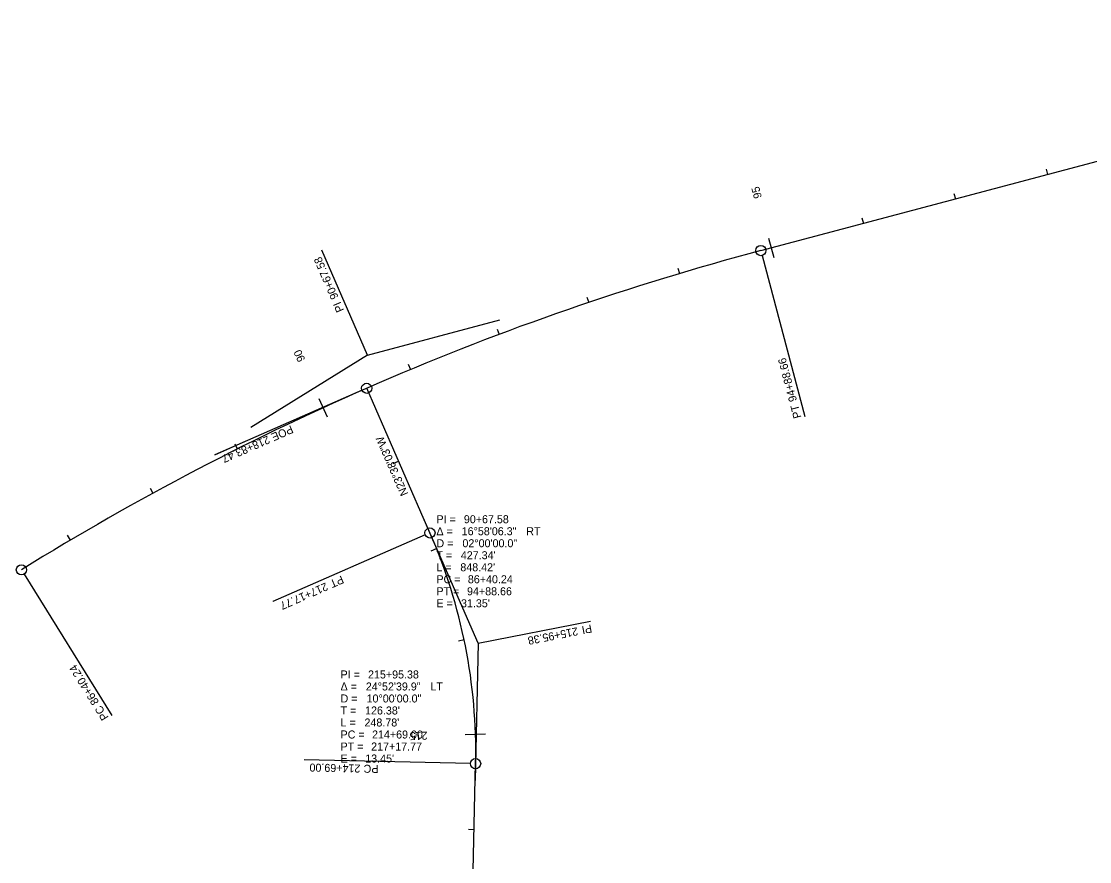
# Model space of a CAD drawing. Extents: x 1145421 to 1155673, y 2015317 to 2021442.
# Drawn here: x 1151212 to 1152333, y 2019901 to 2020782 of the extents above; entities that cross this region are included whole.
import ezdxf

# ---------------------------------------------------------------- set-up
doc = ezdxf.new("R2010")
doc.units = 0
for name, color, linetype in [('Default', 7, 'Continuous'), ('EX_CONTOUR_ANNOT_MINOR', 7, 'Continuous'), ('EX_TERRAIN', 7, 'Continuous')]:
    doc.layers.add(name, color=color, linetype=linetype)

msp = doc.modelspace()

# ---------------------------------------------------------------- linework, layer by layer
at = {"layer": 'Default'}
for p, q in [((1151988, 2020541.8), (1152894.6, 2020782.3)), ((1151640.7, 2020245.5), (1151574.3, 2020397.3)), ((1151677.3, 2019481.5), (1151688.6, 2020003.4))]:
    msp.add_line(p, q, dxfattribs=at)
for centre, radius, start, end in [((1152722.8, 2017772.8), 2864.8, 104.861, 121.8294), ((1151115.8, 2020015.8), 573, 358.7565, 23.6343)]:
    msp.add_arc(centre, radius, start, end, dxfattribs=at)
at = {"layer": 'EX_CONTOUR_ANNOT_MINOR'}
for p, q in [((1152287.4, 2020627.4), (1152288.9, 2020621.6)), ((1152190.7, 2020601.8), (1152192.3, 2020596)), ((1152094.1, 2020576.1), (1152095.6, 2020570.3)), ((1151996.2, 2020555), (1152001.7, 2020534.5)), ((1151575, 2020432.2), (1151527.4, 2020542.4)), ((1151527.4, 2020542.4), (1151527.4, 2020542.4)), ((1151988, 2020541.8), (1151988, 2020541.8)), ((1151989.4, 2020536.6), (1152034.2, 2020367.8)), ((1151901, 2020523.5), (1151902.7, 2020517.7)), ((1151805.5, 2020493.1), (1151807.4, 2020487.4)), ((1151575, 2020432.2), (1151714.1, 2020469.1)), ((1151711.1, 2020459.5), (1151713.2, 2020453.8)), ((1151575, 2020432.2), (1151452.6, 2020356.2)), ((1151617.9, 2020422.5), (1151620.2, 2020417)), ((1151574.3, 2020397.3), (1151574.3, 2020397.3)), ((1151569.4, 2020395.2), (1151414.9, 2020327.6)), ((1151524.2, 2020386.6), (1151533, 2020367.3)), ((1152034.2, 2020367.8), (1152034.2, 2020367.8)), ((1151414.9, 2020327.6), (1151447.8, 2020342)), ((1151435.8, 2020339), (1151438.5, 2020333.6)), ((1151602.2, 2020318.5), (1151607.7, 2020320.9)), ((1151347, 2020292.5), (1151349.9, 2020287.2)), ((1151691.4, 2020129.7), (1151633.6, 2020261.7)), ((1151259.9, 2020243), (1151263, 2020237.8)), ((1151635.8, 2020243.4), (1151475.8, 2020173.4)), ((1151640.7, 2020245.5), (1151640.7, 2020245.5)), ((1151642, 2020226.9), (1151647.6, 2020229.1)), ((1151211.9, 2020206.8), (1151211.9, 2020206.8)), ((1151214.7, 2020202.3), (1151306.8, 2020053.9)), ((1151475.8, 2020173.4), (1151475.8, 2020173.4)), ((1151691.4, 2020129.7), (1151809.1, 2020153)), ((1151809.1, 2020153), (1151809.1, 2020153)), ((1151670.7, 2020132.3), (1151676.5, 2020133.6)), ((1151691.4, 2020129.7), (1151688.2, 2019985.8)), ((1151306.8, 2020053.9), (1151306.8, 2020053.9)), ((1151677.8, 2020034), (1151699, 2020034.7)), ((1151683.3, 2020003.5), (1151508.7, 2020007.3)), ((1151508.7, 2020007.3), (1151508.7, 2020007.3)), ((1151688.6, 2020003.4), (1151688.6, 2020003.4)), ((1151681.1, 2019934.5), (1151687.1, 2019934.4))]:
    msp.add_line(p, q, dxfattribs=at)
for centre in [(1151988, 2020541.8), (1151574.3, 2020397.3), (1151640.7, 2020245.5), (1151211.9, 2020206.8), (1151688.6, 2020003.4)]:
    msp.add_circle(centre, 5.34, dxfattribs=at)
at = {"layer": 'EX_TERRAIN'}
for p, q in [((1151988, 2020541.8), (1152894.6, 2020782.3)), ((1151640.7, 2020245.5), (1151574.3, 2020397.3)), ((1151677.3, 2019481.5), (1151688.6, 2020003.4))]:
    msp.add_line(p, q, dxfattribs=at)
for centre, radius, start, end in [((1152722.8, 2017772.8), 2864.8, 104.861, 121.8294), ((1151115.8, 2020015.8), 573, 358.7565, 23.6343)]:
    msp.add_arc(centre, radius, start, end, dxfattribs=at)

# ---------------------------------------------------------------- texts
at = {"layer": 'EX_CONTOUR_ANNOT_MINOR'}
for s, rotation, p in [('95', 104.861, (1151989.2, 2020597.7)), ('90+67.58', 113.3452, (1151544.9, 2020492.8)), ('PI ', 113.3452, (1151550.7, 2020479.2)), ('90', 114.6343, (1151510.1, 2020427.4)), ('94+88.66', 104.861, (1152026, 2020384.4)), ('PT', 104.861, (1152030.7, 2020366.9)), ('POE ', 203.6343, (1151494.9, 2020358.7)), ('218+83.47', 203.6343, (1151470.4, 2020347.9)), ('N23°38\'03"W', 113.6343, (1151618.1, 2020286.6)), ('217+17.77', 203.6343, (1151531.3, 2020193.7)), ('PT', 203.6343, (1151547.9, 2020201)), ('PI ', 191.1954, (1151809.8, 2020149.5)), ('215+95.38', 191.1954, (1151795.2, 2020146.6)), ('86+40.24', 121.8294, (1151293.7, 2020068.1)), ('PC', 121.8294, (1151303.8, 2020052)), ('215', 181.857, (1151638, 2020037)), ('214+69.00', 178.7565, (1151567.8, 2020002.4)), ('PC', 178.7565, (1151586.8, 2020002))]:
    msp.add_text(s, height=8.4, rotation=rotation, dxfattribs=at).set_placement(p)
for s, p in [('PI = ', (1151647.5, 2020255.7)), ('90+67.58', (1151676.3, 2020255.7)), ('Δ = ', (1151647.5, 2020243.1)), ('16°58\'06.3"', (1151674, 2020243.1)), (' RT', (1151738.7, 2020243.1)), ('D = ', (1151647.5, 2020230.5)), ('02°00\'00.0"', (1151674.8, 2020230.5)), ('T = ', (1151647.5, 2020217.9)), ("427.34'", (1151673.1, 2020217.9)), ('L = ', (1151647.5, 2020205.3)), ("848.42'", (1151672.6, 2020205.3)), ('PC = ', (1151647.5, 2020192.7)), ('86+40.24', (1151680.5, 2020192.7)), ('PT = ', (1151647.5, 2020180.1)), ('94+88.66', (1151679.6, 2020180.1)), ('E = ', (1151647.5, 2020167.5)), ("31.35'", (1151673.3, 2020167.5)), ('PI = ', (1151546.9, 2020092.8)), ('215+95.38', (1151575.7, 2020092.8)), ('Δ = ', (1151546.9, 2020080.2)), ('24°52\'39.9"', (1151573.4, 2020080.2)), (' LT', (1151638.1, 2020080.2)), ('D = ', (1151546.9, 2020067.6)), ('10°00\'00.0"', (1151574.2, 2020067.6)), ('T = ', (1151546.9, 2020055)), ("126.38'", (1151572.6, 2020055)), ('L = ', (1151546.9, 2020042.4)), ("248.78'", (1151572, 2020042.4)), ('PC = ', (1151546.9, 2020029.8)), ('214+69.00', (1151579.9, 2020029.8)), ('PT = ', (1151546.9, 2020017.2)), ('217+17.77', (1151579, 2020017.2)), ('E = ', (1151546.9, 2020004.6)), ("13.45'", (1151572.8, 2020004.6))]:
    msp.add_text(s, height=8.4, dxfattribs=at).set_placement(p)

doc.saveas('drawing.dxf')
